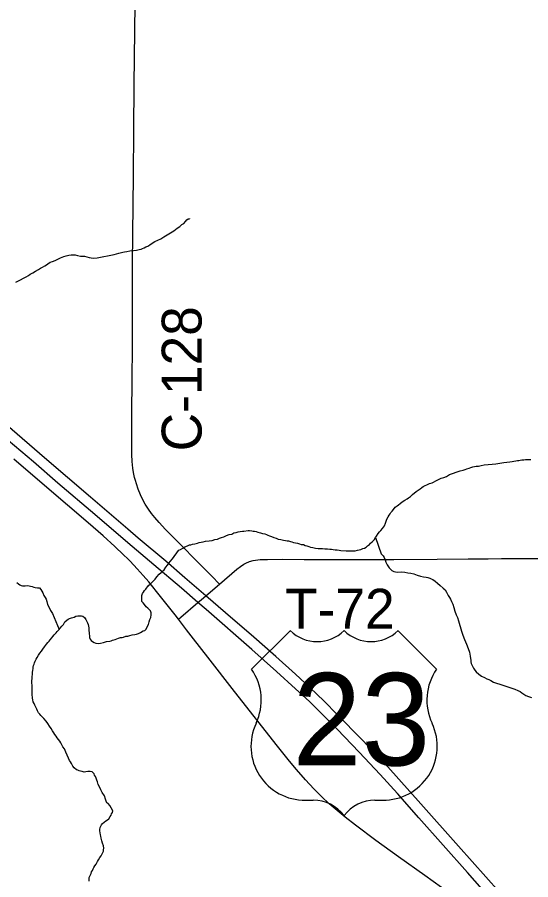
# Model space of a CAD drawing. Extents: x -17 to 88, y -5 to 22.
# Drawn here: x -13.409 to -12.678, y 16.271 to 17.501 of the extents above; entities that cross this region are included whole.
import ezdxf

# ---------------------------------------------------------------- set-up
doc = ezdxf.new("R2010")
doc.units = 0
for name, color, linetype in [('GM_X_County_Road', 7, 'Continuous'), ('GM_X_County_Road_Text', 7, 'Continuous'), ('GM_X_Minor_River', 7, 'Continuous'), ('GM_X_Township_Road', 7, 'Continuous'), ('GM_X_Township_Road_Text', 7, 'Continuous'), ('GM_X_US_Location', 7, 'Continuous'), ('GM_X_US_Route', 7, 'Continuous'), ('GM_X_US_Shield', 7, 'Continuous')]:
    doc.layers.add(name, color=color, linetype=linetype)

msp = doc.modelspace()

# ---------------------------------------------------------------- linework, layer by layer
at = {"layer": 'GM_X_County_Road'}
for points in [[(-13.2457, 16.8773), (-13.2457, 16.8779), (-13.2458, 16.8909), (-13.2456, 16.9294), (-13.2451, 16.9897), (-13.2449, 17.0252), (-13.2448, 17.1165), (-13.2446, 17.1494), (-13.2436, 17.2744), (-13.2429, 17.339), (-13.2424, 17.4042), (-13.2412, 17.5198), (-13.2402, 17.6217), (-13.2392, 17.7032), (-13.2378, 17.7914), (-13.2378, 17.8126), (-13.2378, 17.8337), (-13.2377, 17.8529), (-13.2376, 17.8671)], [(-13.2418, 16.8446), (-13.2432, 16.8514), (-13.2442, 16.8575), (-13.2448, 16.8625), (-13.2452, 16.8674), (-13.2457, 16.8773)], [(-13.2517, 16.7284), (-13.2575, 16.7342), (-13.2702, 16.7461), (-13.2867, 16.7612), (-13.3078, 16.7796), (-13.3667, 16.8302), (-13.414, 16.8705)], [(-13.1207, 16.6925), (-13.1316, 16.7038), (-13.1976, 16.7705), (-13.207, 16.7804), (-13.2131, 16.7874), (-13.2177, 16.7932), (-13.2221, 16.7992), (-13.2267, 16.8065), (-13.2305, 16.8135), (-13.2334, 16.8197), (-13.2366, 16.8277), (-13.2392, 16.8353), (-13.2406, 16.84), (-13.2418, 16.8446)], [(-13.1795, 16.6423), (-13.1841, 16.6485), (-13.205, 16.6747), (-13.2217, 16.6955), (-13.2294, 16.7045), (-13.2381, 16.7142), (-13.2483, 16.725), (-13.2517, 16.7284)], [(-13.1403, 16.6758), (-13.1207, 16.6925)], [(-13.1516, 16.6661), (-13.1466, 16.6703), (-13.1403, 16.6758)], [(-13.1795, 16.6423), (-13.176, 16.6453), (-13.1516, 16.6661)], [(-12.7926, 16.2514), (-12.8285, 16.2771), (-12.866, 16.3036), (-12.8982, 16.327), (-12.9272, 16.3485), (-12.9419, 16.36), (-12.9535, 16.3695), (-12.9647, 16.3793), (-12.9755, 16.3896), (-12.9865, 16.4007), (-12.9984, 16.4134), (-13.0111, 16.4279), (-13.021, 16.4399), (-13.0381, 16.4612), (-13.0995, 16.5395), (-13.1373, 16.5881), (-13.1579, 16.6145), (-13.1679, 16.6272), (-13.1795, 16.6423)]]:
    msp.add_lwpolyline(points, dxfattribs=at)
at = {"layer": 'GM_X_Minor_River'}
for points in [[(-13.4109, 17.123), (-13.4083, 17.1245), (-13.4045, 17.1264), (-13.4003, 17.1287), (-13.3961, 17.1306), (-13.3931, 17.1325), (-13.3905, 17.1344), (-13.387, 17.1363), (-13.3832, 17.1386), (-13.3787, 17.1409), (-13.3757, 17.1428), (-13.373, 17.1443), (-13.3696, 17.1462), (-13.3673, 17.1477), (-13.3654, 17.1492), (-13.362, 17.1515), (-13.359, 17.1526), (-13.3552, 17.1538), (-13.351, 17.1557), (-13.3472, 17.1576), (-13.3426, 17.1595), (-13.3392, 17.1606), (-13.3354, 17.1614), (-13.3324, 17.1621), (-13.3305, 17.1621), (-13.3263, 17.1618), (-13.3233, 17.161), (-13.3191, 17.1599), (-13.3157, 17.1599), (-13.3131, 17.1599), (-13.31, 17.1591), (-13.3066, 17.158), (-13.3036, 17.1576), (-13.3005, 17.1572), (-13.2952, 17.1576), (-13.2709, 17.1622), (-13.2645, 17.1641), (-13.2607, 17.1652), (-13.2588, 17.1656), (-13.2561, 17.1663), (-13.2527, 17.1667), (-13.2485, 17.1675), (-13.2432, 17.1679), (-13.2391, 17.1686), (-13.2353, 17.1694), (-13.2326, 17.1701), (-13.2307, 17.1709), (-13.2284, 17.172), (-13.2258, 17.1732), (-13.2231, 17.1743), (-13.2201, 17.1762), (-13.2167, 17.1785), (-13.2129, 17.1808), (-13.2087, 17.183), (-13.2045, 17.1849), (-13.2004, 17.1876), (-13.1954, 17.1903), (-13.1905, 17.1933), (-13.1859, 17.1963), (-13.1814, 17.1998), (-13.1776, 17.2024), (-13.1746, 17.2051), (-13.1719, 17.2066), (-13.1692, 17.2096), (-13.1673, 17.2119), (-13.1654, 17.2131), (-13.1636, 17.2134), (-13.1636, 17.2138), (-13.1636, 17.2134)], [(-12.7578, 16.86), (-12.7552, 16.8604), (-12.7521, 16.8607), (-12.7483, 16.8615), (-12.7441, 16.8623), (-12.7381, 16.863), (-12.7324, 16.8634), (-12.7271, 16.8638), (-12.7218, 16.8649), (-12.7161, 16.8657), (-12.7115, 16.8664), (-12.7073, 16.8668), (-12.7039, 16.8672), (-12.7017, 16.8676), (-12.699, 16.868), (-12.6963, 16.8687), (-12.6944, 16.8687), (-12.6925, 16.8691), (-12.6903, 16.8695), (-12.6876, 16.8695), (-12.685, 16.8699), (-12.6819, 16.8699), (-12.68, 16.8699), (-12.6774, 16.8702)], [(-13.0371, 16.7566), (-13.0337, 16.7559), (-13.0295, 16.7551), (-13.0268, 16.7544), (-13.0245, 16.754), (-13.0226, 16.754), (-13.0196, 16.7532), (-13.0177, 16.7525), (-13.0154, 16.7517), (-13.0128, 16.7513), (-13.0097, 16.7506), (-13.0071, 16.7498), (-13.0044, 16.749), (-13.001, 16.7487), (-12.9987, 16.7475), (-12.9965, 16.7468), (-12.9938, 16.746), (-12.9912, 16.7453), (-12.9881, 16.7445), (-12.9843, 16.7437), (-12.9805, 16.7434), (-12.9771, 16.743), (-12.9741, 16.743), (-12.971, 16.7426), (-12.9669, 16.7426), (-12.9638, 16.7422), (-12.9612, 16.7422), (-12.9589, 16.7418), (-12.9562, 16.7415), (-12.9532, 16.7411), (-12.9505, 16.7407), (-12.9479, 16.7403), (-12.9403, 16.7399), (-12.938, 16.7399), (-12.935, 16.7399), (-12.9331, 16.7399), (-12.9312, 16.74), (-12.9274, 16.74), (-12.9244, 16.7407), (-12.9221, 16.7411), (-12.9198, 16.7419), (-12.9168, 16.743), (-12.9145, 16.7438), (-12.9122, 16.7453), (-12.9099, 16.7472), (-12.9073, 16.7491), (-12.9058, 16.751), (-12.9035, 16.7529), (-12.9008, 16.7555), (-12.8986, 16.7589), (-12.8974, 16.7608), (-12.8948, 16.7646), (-12.8929, 16.7669), (-12.891, 16.7688), (-12.8887, 16.7715), (-12.8872, 16.7738), (-12.8857, 16.7757), (-12.8845, 16.7795), (-12.8834, 16.7821), (-12.8823, 16.7848), (-12.8807, 16.7882), (-12.8792, 16.7905), (-12.8777, 16.7924), (-12.8766, 16.7943), (-12.8747, 16.7965), (-12.8732, 16.7988), (-12.8705, 16.8019), (-12.8678, 16.8038), (-12.8659, 16.8053), (-12.8637, 16.8072), (-12.8606, 16.8098), (-12.8568, 16.8121), (-12.8538, 16.814), (-12.8515, 16.8155), (-12.8489, 16.8171), (-12.8458, 16.8201), (-12.8409, 16.8243), (-12.8379, 16.8265), (-12.8352, 16.8281), (-12.8329, 16.8303), (-12.8307, 16.8315), (-12.828, 16.833), (-12.8257, 16.8341), (-12.8219, 16.8357), (-12.82, 16.8364), (-12.8178, 16.8368), (-12.8159, 16.8379), (-12.8128, 16.8398), (-12.8087, 16.8414), (-12.8049, 16.8433), (-12.8011, 16.8444), (-12.7973, 16.8459), (-12.7931, 16.8486), (-12.7783, 16.8539), (-12.7737, 16.855), (-12.7711, 16.8558), (-12.7684, 16.8566), (-12.7654, 16.8577), (-12.7631, 16.8585), (-12.7601, 16.8596), (-12.7578, 16.86)], [(-13.2647, 16.6153), (-13.2617, 16.6161), (-13.2594, 16.6165), (-13.2575, 16.6169), (-13.2541, 16.618), (-13.2514, 16.6184), (-13.2484, 16.6191), (-13.2454, 16.6199), (-13.2416, 16.6207), (-13.2389, 16.621), (-13.2363, 16.6218), (-13.2332, 16.6233), (-13.2294, 16.6256), (-13.2271, 16.6264), (-13.2252, 16.6283), (-13.2237, 16.6313), (-13.2222, 16.6347), (-13.2211, 16.6385), (-13.2199, 16.6419), (-13.2188, 16.645), (-13.2184, 16.6488), (-13.218, 16.6514), (-13.2192, 16.6545), (-13.2211, 16.6564), (-13.223, 16.6579), (-13.2253, 16.6602), (-13.2275, 16.6632), (-13.2294, 16.6655), (-13.2313, 16.6677), (-13.2317, 16.6723), (-13.2313, 16.6761), (-13.2306, 16.6791), (-13.2291, 16.681), (-13.2275, 16.6833), (-13.226, 16.6852), (-13.2226, 16.6898), (-13.2188, 16.6932), (-13.2154, 16.6966), (-13.2127, 16.6996), (-13.2101, 16.7027), (-13.2067, 16.7065), (-13.204, 16.7091), (-13.2021, 16.7107), (-13.1998, 16.7129), (-13.1972, 16.7167), (-13.1949, 16.7194), (-13.193, 16.7221), (-13.1907, 16.7251), (-13.1885, 16.7278), (-13.1866, 16.7304), (-13.1847, 16.7331), (-13.1828, 16.7357), (-13.1809, 16.7384), (-13.179, 16.7407), (-13.1763, 16.7418), (-13.1733, 16.7437), (-13.1703, 16.7456), (-13.1665, 16.7471), (-13.1634, 16.7483), (-13.1615, 16.7486), (-13.1593, 16.7494), (-13.1562, 16.7498), (-13.1543, 16.7502), (-13.1524, 16.7509), (-13.1498, 16.7517), (-13.1471, 16.7524), (-13.1441, 16.7528), (-13.1407, 16.7536), (-13.1357, 16.754), (-13.1312, 16.7547), (-13.1274, 16.7559), (-13.1236, 16.7566), (-13.1209, 16.7578), (-13.1179, 16.7589), (-13.1149, 16.76), (-13.1107, 16.7616), (-13.1069, 16.7631), (-13.1035, 16.7638), (-13.1004, 16.7654), (-13.097, 16.7661), (-13.0944, 16.7669), (-13.0913, 16.7676), (-13.0879, 16.768), (-13.086, 16.768), (-13.08, 16.7688), (-13.0781, 16.7688), (-13.0746, 16.7684), (-13.0727, 16.768), (-13.0708, 16.768), (-13.0686, 16.7676), (-13.0663, 16.7665), (-13.0625, 16.7657), (-13.0595, 16.7646), (-13.0564, 16.7639), (-13.0541, 16.7631), (-13.0519, 16.7623), (-13.0496, 16.7612), (-13.0466, 16.7601), (-13.0435, 16.7589), (-13.0401, 16.7578), (-13.0371, 16.7566)], [(-12.8986, 16.7589), (-12.8906, 16.7358), (-12.8879, 16.7327), (-12.8864, 16.7305), (-12.8849, 16.727), (-12.8838, 16.7236), (-12.8819, 16.7198), (-12.8792, 16.7157), (-12.8754, 16.7119), (-12.8724, 16.7103), (-12.8701, 16.71), (-12.8671, 16.7096), (-12.8621, 16.71), (-12.8568, 16.7096), (-12.8526, 16.7084), (-12.8485, 16.7081), (-12.8439, 16.7069), (-12.8394, 16.7054), (-12.8348, 16.7039), (-12.8302, 16.7028), (-12.8265, 16.7024), (-12.8242, 16.7016), (-12.8215, 16.7009), (-12.8192, 16.7001), (-12.817, 16.699), (-12.8139, 16.6967), (-12.8105, 16.6936), (-12.8067, 16.6902), (-12.8025, 16.6868), (-12.7995, 16.6842), (-12.7976, 16.6811), (-12.7953, 16.6762), (-12.7934, 16.6735), (-12.7919, 16.6709), (-12.7904, 16.6674), (-12.7885, 16.664), (-12.787, 16.6591), (-12.7855, 16.6538), (-12.7836, 16.6488), (-12.782, 16.6447), (-12.7805, 16.6401), (-12.7763, 16.6253), (-12.7741, 16.6196), (-12.7718, 16.6135), (-12.7691, 16.6067), (-12.7665, 16.6006), (-12.765, 16.5953), (-12.7638, 16.5896), (-12.7634, 16.5862), (-12.7631, 16.5839), (-12.7627, 16.5816), (-12.7623, 16.5794), (-12.7615, 16.5775), (-12.7604, 16.5756), (-12.7589, 16.5725), (-12.757, 16.5699), (-12.7551, 16.5672), (-12.7517, 16.5642), (-12.7475, 16.5611), (-12.7433, 16.5592), (-12.7399, 16.5573), (-12.7372, 16.5562), (-12.7342, 16.5551), (-12.7304, 16.5528), (-12.7171, 16.5482), (-12.7114, 16.5463), (-12.7057, 16.5444), (-12.7004, 16.5425), (-12.6959, 16.5406), (-12.6928, 16.5391), (-12.6902, 16.5376), (-12.6875, 16.5357), (-12.6845, 16.5338), (-12.6807, 16.5323), (-12.6765, 16.5308)], [(-13.4097, 16.6947), (-13.4074, 16.6928), (-13.4051, 16.6913), (-13.4032, 16.6905), (-13.4013, 16.6901), (-13.3975, 16.6901), (-13.3945, 16.6905), (-13.3922, 16.6901), (-13.39, 16.6894), (-13.3877, 16.689), (-13.3854, 16.6882), (-13.3835, 16.6875), (-13.3801, 16.6871), (-13.3771, 16.6871), (-13.3752, 16.6848), (-13.374, 16.6825), (-13.3725, 16.6799)], [(-13.3725, 16.6799), (-13.371, 16.6761), (-13.3691, 16.6734), (-13.3679, 16.6708), (-13.3668, 16.6677), (-13.3657, 16.6632), (-13.3634, 16.659), (-13.3615, 16.6548), (-13.3588, 16.6503), (-13.3493, 16.6279)], [(-13.3485, 16.4684), (-13.3501, 16.471), (-13.352, 16.4733), (-13.3535, 16.4756), (-13.3554, 16.4779), (-13.3569, 16.4805), (-13.3588, 16.4832), (-13.3607, 16.4866), (-13.363, 16.49), (-13.3656, 16.4938), (-13.3679, 16.4972), (-13.3713, 16.501), (-13.3736, 16.5033), (-13.3755, 16.5052), (-13.377, 16.5071), (-13.3785, 16.509), (-13.38, 16.5117), (-13.3812, 16.5143), (-13.3827, 16.517), (-13.3838, 16.5196), (-13.385, 16.5223), (-13.3861, 16.5246), (-13.3869, 16.5272), (-13.3873, 16.5299), (-13.3873, 16.5318), (-13.3876, 16.5337), (-13.3876, 16.536), (-13.3876, 16.5451), (-13.3876, 16.5485), (-13.388, 16.5511), (-13.388, 16.5546), (-13.3876, 16.558), (-13.3876, 16.5606), (-13.3873, 16.5637), (-13.3873, 16.5667), (-13.3869, 16.5694), (-13.3865, 16.572), (-13.3861, 16.5739), (-13.3858, 16.5762), (-13.385, 16.5785), (-13.3842, 16.5804), (-13.3835, 16.5827), (-13.382, 16.5853), (-13.3804, 16.588), (-13.3785, 16.591), (-13.3766, 16.5941), (-13.3744, 16.5967), (-13.3725, 16.5998), (-13.3702, 16.6028), (-13.3675, 16.6066), (-13.3653, 16.6092), (-13.3634, 16.6111), (-13.3619, 16.613), (-13.3596, 16.6157), (-13.3581, 16.6176), (-13.3562, 16.6199), (-13.3535, 16.6229), (-13.352, 16.6248), (-13.3493, 16.6279), (-13.3478, 16.6298), (-13.3455, 16.6324), (-13.3429, 16.6347), (-13.341, 16.6385), (-13.3383, 16.6411), (-13.3364, 16.6423), (-13.3345, 16.6434), (-13.3319, 16.6442), (-13.3281, 16.6453), (-13.3254, 16.6465), (-13.3228, 16.6472), (-13.3205, 16.6472), (-13.3175, 16.6472), (-13.3156, 16.6465), (-13.3133, 16.6446), (-13.3114, 16.6419), (-13.3099, 16.6389), (-13.3091, 16.637), (-13.308, 16.6347), (-13.3076, 16.6324), (-13.3072, 16.6301), (-13.3072, 16.6282), (-13.3068, 16.626), (-13.3065, 16.6233), (-13.3065, 16.621), (-13.3061, 16.6191), (-13.3061, 16.6161), (-13.3053, 16.6138), (-13.3038, 16.6119), (-13.3019, 16.6108), (-13.2996, 16.6093), (-13.297, 16.6081), (-13.2936, 16.6077), (-13.2905, 16.6081), (-13.2863, 16.6093), (-13.2818, 16.6104), (-13.2772, 16.6112), (-13.2753, 16.6115), (-13.2731, 16.6123), (-13.2693, 16.6134), (-13.267, 16.6146), (-13.2647, 16.6153)], [(-13.3064, 16.269), (-13.3067, 16.2721), (-13.3064, 16.274), (-13.3056, 16.2762), (-13.3048, 16.2781), (-13.3037, 16.28), (-13.303, 16.2823), (-13.3018, 16.2842), (-13.3007, 16.2865), (-13.2999, 16.2884), (-13.2984, 16.2907), (-13.2965, 16.2933), (-13.2946, 16.2967), (-13.2931, 16.2994), (-13.2912, 16.3024), (-13.2893, 16.3051), (-13.2885, 16.307), (-13.2874, 16.3089), (-13.2863, 16.3115), (-13.2859, 16.3134), (-13.2855, 16.3161), (-13.2863, 16.3191), (-13.2874, 16.3229), (-13.2885, 16.3264), (-13.2893, 16.3302), (-13.2901, 16.3328), (-13.2904, 16.3351), (-13.2908, 16.3377), (-13.2912, 16.3408), (-13.2912, 16.3427), (-13.2908, 16.3453), (-13.2889, 16.3491), (-13.2874, 16.351), (-13.2829, 16.3548), (-13.2806, 16.3564), (-13.2787, 16.3579), (-13.2764, 16.3609), (-13.2753, 16.3628), (-13.2745, 16.3647), (-13.2734, 16.3666), (-13.273, 16.3693), (-13.2753, 16.3734), (-13.2772, 16.3769), (-13.2794, 16.3795), (-13.2813, 16.3807), (-13.2821, 16.3829), (-13.2832, 16.3856), (-13.2848, 16.3905), (-13.2878, 16.3955), (-13.2901, 16.3993), (-13.292, 16.4034), (-13.2935, 16.4069), (-13.2946, 16.4103), (-13.2954, 16.4129), (-13.2965, 16.4156), (-13.2977, 16.4179), (-13.2988, 16.4198), (-13.2996, 16.422), (-13.3022, 16.4247), (-13.3053, 16.4251), (-13.3083, 16.4251), (-13.3113, 16.4247), (-13.3136, 16.4243), (-13.3166, 16.4251), (-13.3189, 16.4255), (-13.3208, 16.4262), (-13.3227, 16.427), (-13.3246, 16.4277), (-13.3277, 16.4304), (-13.3296, 16.4327), (-13.3307, 16.4346), (-13.3318, 16.4365), (-13.3333, 16.4388), (-13.3345, 16.441), (-13.336, 16.4444), (-13.3379, 16.4486), (-13.3398, 16.4528), (-13.3417, 16.4574), (-13.344, 16.4604), (-13.3455, 16.4631), (-13.347, 16.4661), (-13.3485, 16.4684)]]:
    msp.add_lwpolyline(points, dxfattribs=at)
at = {"layer": 'GM_X_Township_Road'}
for points in [[(-13.1207, 16.6925), (-13.0964, 16.7135), (-13.091, 16.7177), (-13.0862, 16.7208), (-13.0834, 16.7224), (-13.0782, 16.7246), (-13.0727, 16.7261), (-13.0665, 16.7271), (-13.063, 16.7274)], [(-13.063, 16.7274), (-13.0602, 16.7276), (-13.0527, 16.7277), (-13.031, 16.7278), (-13.0005, 16.7277), (-12.9651, 16.7276), (-12.9278, 16.7274), (-12.8725, 16.7274), (-12.811, 16.7279), (-12.7668, 16.7284), (-12.7383, 16.7286), (-12.719, 16.7288), (-12.6649, 16.7289)]]:
    msp.add_lwpolyline(points, dxfattribs=at)
at = {"layer": 'GM_X_US_Route'}
for points in [[(-12.7028, 16.2312), (-12.7803, 16.3186), (-12.8341, 16.3789), (-12.8813, 16.4317), (-12.8973, 16.4491), (-12.9187, 16.4715), (-12.9526, 16.5062), (-12.9724, 16.526), (-12.9917, 16.5445), (-13.0126, 16.564), (-13.0406, 16.5894), (-13.072, 16.617), (-13.1122, 16.6516), (-13.1403, 16.6758), (-13.1701, 16.7014), (-13.1975, 16.7249), (-13.2366, 16.758), (-13.2514, 16.7707), (-13.3045, 16.8163), (-13.3701, 16.8726), (-13.4232, 16.9185)], [(-12.7396, 16.2495), (-12.7677, 16.2811), (-12.8368, 16.3594), (-12.8675, 16.3937), (-12.8922, 16.4208), (-12.9219, 16.4526), (-12.9532, 16.4854), (-12.9729, 16.5053), (-12.9929, 16.5249), (-13.0124, 16.5432), (-13.0395, 16.5679), (-13.0747, 16.5994), (-13.1399, 16.656), (-13.1516, 16.6661), (-13.1752, 16.6865), (-13.2146, 16.7198), (-13.2515, 16.7515), (-13.2986, 16.7918), (-13.3512, 16.8365), (-13.3859, 16.8666), (-13.4217, 16.8974)]]:
    msp.add_lwpolyline(points, dxfattribs=at)
at = {"layer": 'GM_X_US_Shield'}
for p, q in [((-13.0203, 16.626), (-13.0753, 16.5711)), ((-12.8116, 16.5711), (-12.8665, 16.626)), ((-12.9984, 16.3843), (-12.9874, 16.3843)), ((-12.8995, 16.3843), (-12.8885, 16.3843))]:
    msp.add_line(p, q, dxfattribs=at)
for centre, radius, start, end in [((-12.9819, 16.6653), 0.0549, 225.573, 314.427), ((-12.905, 16.6653), 0.0549, 225.573, 314.427), ((-13.1383, 16.527), 0.0769, 334.5471, 35.0009), ((-12.7486, 16.527), 0.0769, 144.9991, 205.4529), ((-12.9992, 16.4612), 0.0769, 154.8319, 270.6383), ((-12.8876, 16.4612), 0.0769, 269.3617, 25.1681), ((-12.9874, 16.3294), 0.0549, 36.8699, 90), ((-12.8995, 16.3294), 0.0549, 90, 143.1301)]:
    msp.add_arc(centre, radius, start, end, dxfattribs=at)

# ---------------------------------------------------------------- texts
at = {"layer": 'GM_X_County_Road_Text'}
msp.add_text('C-128', height=0.05682, rotation=90, dxfattribs=at).set_placement((-13.1464, 16.8817))
at = {"layer": 'GM_X_Township_Road_Text'}
msp.add_text('T-72', height=0.05682, rotation=0, dxfattribs=at).set_placement((-13.0276, 16.6289))
at = {"layer": 'GM_X_US_Location'}
for s in ['/', '0']:
    msp.add_text(s, height=0.000189, dxfattribs=at).set_placement((-12.9435, 16.4987))
msp.add_text('23', height=0.000189, rotation=0, dxfattribs=at).set_placement((-12.9826, 16.4594))
at = {"layer": 'GM_X_US_Shield'}
msp.add_text('23', height=0.13184, dxfattribs=at).set_placement((-13.0168, 16.4338))

doc.saveas('drawing.dxf')
